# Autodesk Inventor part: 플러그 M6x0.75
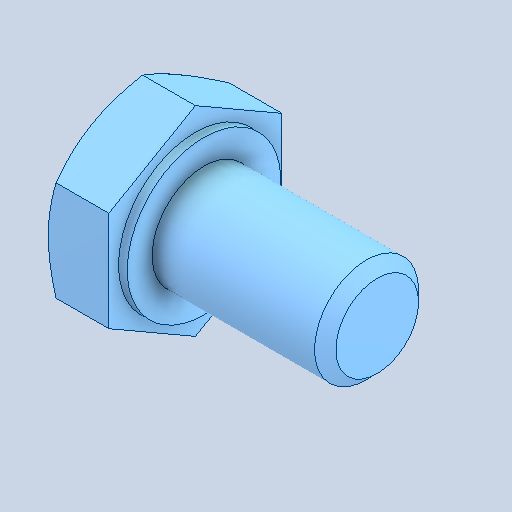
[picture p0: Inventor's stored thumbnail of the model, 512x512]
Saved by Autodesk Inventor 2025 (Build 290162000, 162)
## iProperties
Created: 2026-03
Part Number: 플러그 M6x0.75
Material: 강철, 연강
Description: 6각 머리 볼트 및 6각 머리 나사
Document SubType Name: Modeling
Designer: KDI
Density: 7.85 g/cm^3
Appearance: 기본값
Author: jhkim
Sending System: Autodesk Inventor 2026
Preprocessor: ST-DEVELOPER v20.1
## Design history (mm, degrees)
feature "Solid1"
node "솔리드1"
